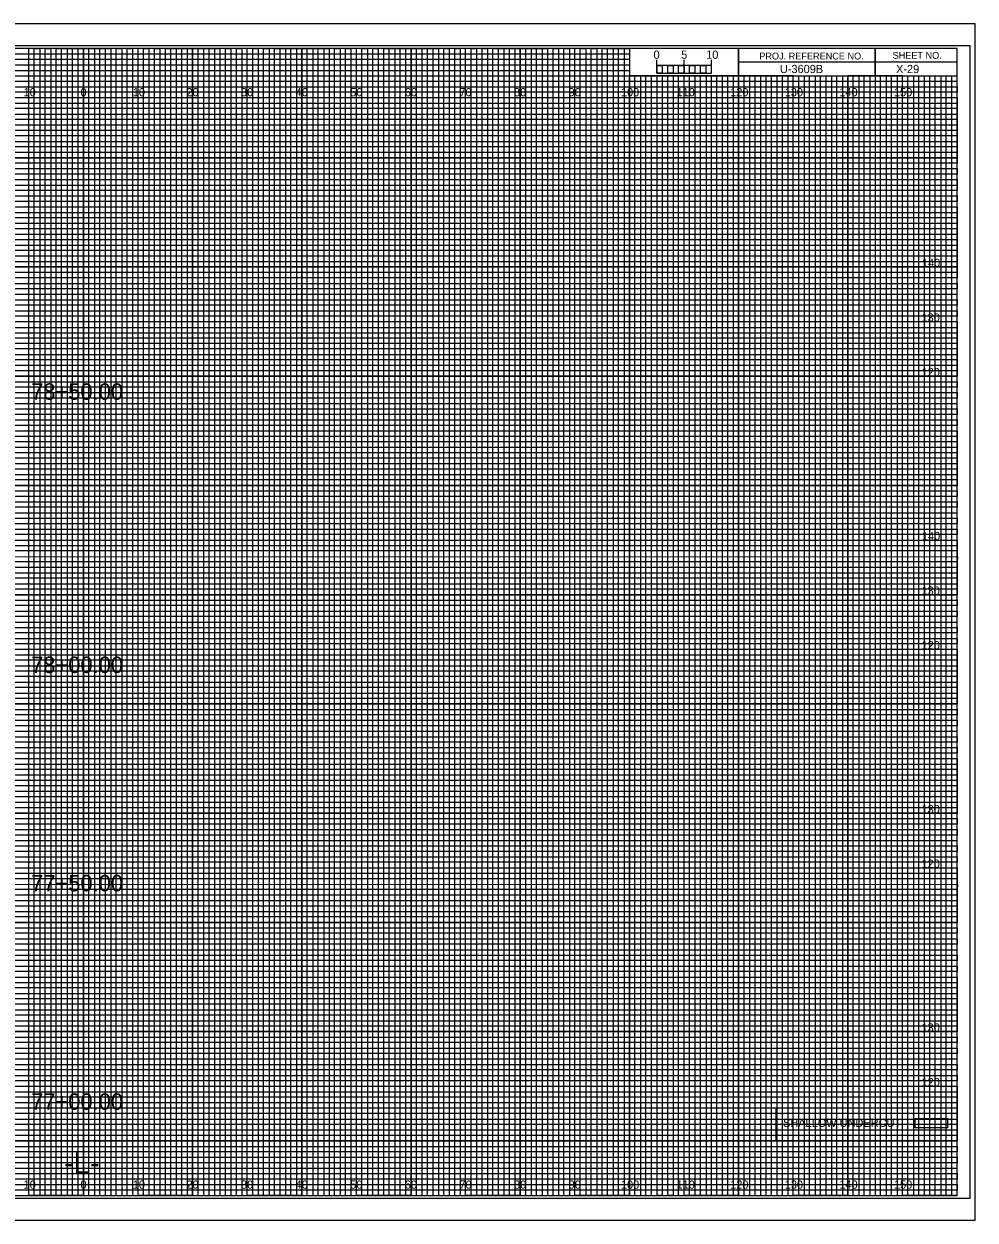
# Model space of a CAD drawing. Extents: x -13 to 329, y -17 to 10994.
# Drawn here: x 149.1 to 323.3, y 5935.5 to 6154.5 of the extents above; entities that cross this region are included whole.
import ezdxf

# ---------------------------------------------------------------- set-up
doc = ezdxf.new("R2010")
doc.units = 0
for name, color, linetype in [('Prop DSN Text', 7, 'Continuous'), ('Prop Grid Mask', 7, 'Continuous'), ('Prop Road Plan_ Recs - UC Shallow (pattern)', 7, 'Continuous'), ('Prop XS Alignment Label', 7, 'Continuous'), ('Prop XS Bar Scale Labels', 7, 'Continuous'), ('Prop XS Elevation Labels', 7, 'Continuous'), ('Prop XS Offset Labels', 7, 'Continuous'), ('Prop XS Project Number', 7, 'Continuous'), ('Prop XS Sheet Number', 7, 'Continuous'), ('Prop XS Station Labels', 7, 'Continuous'), ('Sheet Cross Section CELL', 7, 'Continuous'), ('Sheet Cross Section Grid Major CELL', 7, 'Continuous'), ('Sheet Cross Section Grid Middle CELL', 7, 'Continuous'), ('Sheet Cross Section Grid Minor 1 CELL', 7, 'Continuous'), ('Sheet Cross Section Grid Minor 2 CELL', 7, 'Continuous'), ('Sheet Cross Section Scale CELL', 7, 'Continuous'), ('Sheet Cutting Line CELL', 7, 'Continuous'), ('Sheet DOT Grid CELL', 7, 'Continuous'), ('Sheet Plot Border Inside CELL', 7, 'Continuous'), ('Sheet Plot Border Outside CELL', 7, 'Continuous')]:
    doc.layers.add(name, color=color, linetype=linetype)

msp = doc.modelspace()

# ---------------------------------------------------------------- linework, layer by layer
at = {"layer": 'Prop Grid Mask'}
msp.add_lwpolyline([(286.89, 5956.03), (320, 5956.03), (320, 5950), (286.89, 5950)], close=True, dxfattribs=at)
at = {"layer": 'Prop Road Plan_ Recs - UC Shallow (pattern)'}
msp.add_lwpolyline([(312.34, 5954.08), (318.23, 5954.08), (318.23, 5952.36), (312.34, 5952.36)], close=True, dxfattribs=at)
at = {"layer": 'Sheet Cross Section CELL'}
for p, q in [((305, 6150), (305, 6145)), ((305, 6145), (305, 6150)), ((280, 6147.5), (280, 6145)), ((320, 6147.49), (280, 6147.49)), ((280, 6145), (320, 6145))]:
    msp.add_line(p, q, dxfattribs=at)
for points in [[(320, 6150), (0, 6150), (0, 5940), (320, 5940)], [(280, 6150), (260, 6150), (260, 6145.03), (280, 6145.03)], [(320, 6150), (280, 6150), (280, 6145), (320, 6145)]]:
    msp.add_lwpolyline(points, close=True, dxfattribs=at)
at = {"layer": 'Sheet Cross Section Grid Major CELL'}
for p, q in [((150, 6150), (140, 6150)), ((150, 5940), (150, 6150)), ((170, 6150), (160, 6150)), ((160, 6150), (160, 5940)), ((170, 5940), (170, 6150)), ((190, 6150), (180, 6150)), ((180, 6150), (180, 5940)), ((190, 5940), (190, 6150)), ((210, 6150), (200, 6150)), ((200, 6150), (200, 5940)), ((210, 5940), (210, 6150)), ((230, 6150), (220, 6150)), ((220, 6150), (220, 5940)), ((230, 5940), (230, 6150)), ((250, 6150), (240, 6150)), ((240, 6150), (240, 5940)), ((250, 5940), (250, 6150)), ((260, 6150), (260, 5940)), ((270, 5940), (270, 6145)), ((290, 6145), (280, 6145)), ((280, 6145), (280, 5940)), ((290, 5940), (290, 6145)), ((310, 6145), (300, 6145)), ((300, 6145), (300, 5940)), ((310, 5940), (310, 6145)), ((160, 5940), (150, 5940)), ((180, 5940), (170, 5940)), ((200, 5940), (190, 5940)), ((220, 5940), (210, 5940)), ((240, 5940), (230, 5940)), ((260, 5940), (250, 5940)), ((280, 5940), (270, 5940)), ((300, 5940), (290, 5940)), ((320, 5940), (310, 5940)), ((320, 5940), (320, 5940))]:
    msp.add_line(p, q, dxfattribs=at)
for points in [[(0, 6140), (320, 6140), (320, 6130), (0, 6130)], [(0, 6120), (320, 6120), (320, 6110), (0, 6110)], [(0, 6100), (320, 6100), (320, 6090), (0, 6090)], [(0, 6080), (320, 6080), (320, 6070), (0, 6070)], [(0, 6060), (320, 6060), (320, 6050), (0, 6050)], [(0, 6040), (320, 6040), (320, 6030), (0, 6030)], [(0, 6020), (320, 6020), (320, 6010), (0, 6010)], [(0, 6000), (320, 6000), (320, 5990), (0, 5990)], [(0, 5980), (320, 5980), (320, 5970), (0, 5970)], [(0, 5960), (320, 5960), (320, 5950), (0, 5950)]]:
    msp.add_lwpolyline(points, dxfattribs=at)
at = {"layer": 'Sheet Cross Section Grid Middle CELL'}
for points in [[(145, 5940), (155, 5940), (155, 6150), (165, 6150), (165, 5940), (175, 5940), (175, 6150), (185, 6150), (185, 5940), (195, 5940), (195, 6150), (205, 6150), (205, 5940), (215, 5940), (215, 6150), (225, 6150), (225, 5940), (235, 5940), (235, 6150), (245, 6150), (245, 5940), (255, 5940), (255, 6150), (259.93, 6150), (260, 6150), (260, 6145), (264.99, 6145), (264.99, 5940), (275, 5940), (275, 6145), (285, 6145), (285, 5940), (295, 5940), (295, 6145), (305, 6145), (305, 5940), (315, 5940), (315, 6145)], [(0, 6145), (275, 6145)], [(0, 6125), (320, 6125), (320, 6135), (0, 6135)], [(0, 6105), (320, 6105), (320, 6115), (0, 6115)], [(0, 6085), (320, 6085), (320, 6095), (0, 6095)], [(0, 6065), (320, 6065), (320, 6075), (0, 6075)], [(0, 6045), (320, 6045), (320, 6055), (0, 6055)], [(0, 6025), (320, 6025), (320, 6035), (0, 6035)], [(0, 6005), (320, 6005), (320, 6015), (0, 6015)], [(0, 5985), (320, 5985), (320, 5995), (0, 5995)], [(0, 5965), (320, 5965), (320, 5975), (0, 5975)], [(0, 5945), (320, 5945), (320, 5955), (0, 5955)]]:
    msp.add_lwpolyline(points, dxfattribs=at)
at = {"layer": 'Sheet Cross Section Grid Minor 1 CELL'}
for p, q in [((0, 6149), (260, 6149)), ((260, 6147.98), (0, 6147.98)), ((260, 6149), (260, 6147.98)), ((0, 6147), (260, 6147)), ((260, 6145.89), (0, 6145.89)), ((260, 6147), (260, 6145.89)), ((0, 6144), (320, 6144))]:
    msp.add_line(p, q, dxfattribs=at)
for points in [[(0, 6143), (270, 6143), (320, 6143), (320, 6142), (0, 6142)], [(0, 6141), (320, 6141), (320, 6139), (0, 6139)], [(0, 6138), (320, 6138), (320, 6137), (0, 6136.98)], [(0, 6136), (320, 6136), (320, 6134), (0, 6134)], [(0, 6133), (320, 6133), (320, 6132), (0, 6132)], [(0, 6131), (320, 6131), (320, 6129), (0, 6129)], [(0, 6128), (320, 6128), (320, 6127), (0, 6127)], [(0, 6126), (320, 6126), (320, 6124), (0, 6124)], [(0, 6123), (320, 6123), (320, 6122), (0, 6122)], [(0, 6121), (320, 6121), (320, 6119), (0, 6119)], [(0, 6118), (320, 6118), (320, 6117), (0, 6117)], [(0, 6116), (320, 6116), (320, 6113.95), (320, 6113), (320, 6112), (0, 6112)], [(0, 6114), (320, 6114), (320, 6113), (0, 6113)], [(0, 6111), (320, 6111), (320, 6109), (0, 6109.03)], [(0, 6109.03), (320, 6109), (320, 6108), (0, 6108)], [(0, 6107), (320, 6107), (320, 6106), (0, 6106)], [(0, 6104), (320, 6104), (320, 6103), (0, 6103)], [(0, 6102), (320, 6102), (320, 6101), (0, 6101)], [(-0.07, 6098.89), (320, 6098.89), (320, 6097.88), (-0.07, 6097.88)], [(0, 6097), (320, 6097), (320, 6096), (0, 6096)], [(0, 6094), (320, 6094), (320, 6093), (0, 6093)], [(0, 6092), (320, 6092), (320, 6091), (0, 6091)], [(0, 6089), (320, 6089), (320, 6088), (0, 6088)], [(0, 6087), (320, 6087), (320, 6086), (0, 6086)], [(0, 6084), (320, 6084), (320, 6083), (0, 6083)], [(0, 6082), (320, 6082), (320, 6081), (0, 6081)], [(0, 6079), (320, 6079), (319.99, 6077.98), (0, 6078)], [(0, 6077), (320, 6077), (320, 6076), (0, 6076)], [(0, 6074), (320, 6074), (320, 6073), (0, 6073)], [(0, 6072), (320, 6072), (320, 6071), (0, 6071)], [(0, 6069), (320, 6069), (320, 6068), (0, 6068)], [(0, 6067), (320, 6067), (320, 6066), (0, 6066)], [(0, 6064), (320, 6064), (320, 6063), (0, 6063)], [(0, 6062), (320, 6062), (320, 6061), (0, 6061)], [(0, 6059), (320, 6059), (320, 6058), (0, 6058)], [(0, 6056.99), (320.07, 6056.91), (320, 6056), (0, 6056)], [(0, 6054), (320, 6054), (320, 6053), (0, 6053)], [(0, 6052), (320, 6052), (320, 6051), (0, 6051)], [(0, 6049), (320, 6049), (320, 6048), (0, 6048)], [(0, 6047), (320, 6047), (320, 6046), (0, 6046)], [(0, 6044), (320, 6044), (320, 6043), (0, 6043)], [(0, 6042), (320, 6042), (320, 6041), (0, 6041)], [(0, 6039), (320, 6039), (320, 6038), (0, 6038)], [(0, 6037), (320, 6037), (320, 6036), (0, 6036)], [(0, 6034), (320, 6034), (320, 6033), (0, 6033)], [(0, 6032), (320, 6032), (320, 6031), (0, 6031)], [(0, 6029), (320, 6029), (320, 6028), (0, 6028)], [(0, 6027), (320, 6027), (320, 6026), (0, 6026)], [(0, 6024), (320, 6024), (320, 6023), (0, 6023)], [(0, 6022), (320, 6022), (320, 6021), (0, 6021)], [(0, 6019), (320, 6019), (319.99, 6017.98), (0, 6018)], [(0, 6017), (320, 6017), (320, 6016), (0, 6016)], [(0, 6014), (320, 6014), (320, 6013), (0, 6013)], [(0, 6012), (320, 6012), (320, 6011), (0, 6011)], [(0, 6009), (320, 6009), (320, 6008), (0, 6008)], [(0, 6007), (320, 6007), (320, 6006), (0, 6006)], [(0, 6004), (320, 6004), (320, 6003), (0, 6003)], [(0, 6002), (320, 6002), (320, 6001), (0, 6001)], [(0, 5999), (320, 5999), (320, 5998), (0, 5998)], [(0, 5996.99), (320.07, 5996.91), (320, 5996), (0, 5996)], [(0, 5994), (320, 5994), (320, 5993), (0, 5993)], [(0, 5992), (320, 5992), (320, 5991), (0, 5991)], [(0, 5989), (320, 5989), (320, 5988), (0, 5988)], [(0, 5987), (320, 5987), (320, 5986), (0, 5986)], [(0, 5984), (320, 5984), (320, 5983), (0, 5983)], [(0, 5982), (320, 5982), (320, 5981), (0, 5981)], [(0, 5979), (320, 5979), (320, 5978), (0, 5978)], [(0, 5977), (320, 5977), (320, 5976), (0, 5976)], [(0, 5974), (320, 5974), (320, 5973), (0, 5973)], [(0, 5972), (320, 5972), (320, 5971), (0, 5971)], [(0, 5969), (320, 5969), (320, 5968), (0, 5968)], [(0, 5967), (320, 5967), (320, 5966), (0, 5966)], [(0, 5964), (320, 5964), (320, 5963), (0, 5963)], [(0, 5962), (320, 5962), (320, 5961), (0, 5961)], [(0, 5959), (320, 5959), (320, 5958), (0, 5958)], [(0, 5957), (320, 5957), (320, 5956), (0, 5956)], [(0, 5954), (320, 5954), (320, 5953), (0, 5953)], [(0, 5952), (320, 5952), (320, 5951), (0, 5951)], [(0, 5949), (320, 5949), (320, 5948), (0, 5948)], [(0, 5947), (320, 5947), (320, 5946), (0, 5946)], [(0, 5944), (320, 5944), (320, 5943), (0, 5943)], [(0, 5942), (320, 5942), (320, 5941), (0, 5941)]]:
    msp.add_lwpolyline(points, dxfattribs=at)
at = {"layer": 'Sheet Cross Section Grid Minor 2 CELL'}
for p, q in [((267, 6145), (266.01, 6145)), ((266.01, 6145), (266.01, 5940)), ((267, 5940), (267, 6145)), ((269, 6145), (268, 6145)), ((268, 6145), (268, 5940)), ((269, 5940), (269, 6145)), ((266.01, 5940), (265, 5940)), ((268, 5940), (267, 5940))]:
    msp.add_line(p, q, dxfattribs=at)
for points in [[(150, 5940), (151, 5940), (151, 6150), (152, 6150), (152, 5940)], [(152, 5940), (153, 5940), (153, 6150), (154, 6150), (154, 5940)], [(155, 5940), (156, 5940), (156, 6150), (157, 6150), (157, 5940)], [(157, 5940), (158, 5940), (158, 6150), (159, 6150), (159, 5940)], [(160, 5940), (161, 5940), (161, 6150), (162, 6150), (162, 5940)], [(162, 5940), (163, 5940), (163, 6150), (164, 6150), (164, 5940)], [(165, 5940), (166, 5940), (166, 6150), (167, 6150), (167, 5940)], [(167, 5940), (168, 5940), (168, 6150), (169, 6150), (169, 5940)], [(170, 5940), (171, 5940), (171, 6150), (172, 6150), (172, 5940)], [(172, 5940), (173, 5940), (173, 6150), (174, 6150), (174, 5940)], [(175, 5940), (176, 5940), (176, 6150), (177, 6150), (177, 5940)], [(177, 5940), (178, 5940), (178, 6150), (179, 6150), (179, 5940)], [(180, 5940), (181, 5940), (181, 6150), (182, 6150), (182, 5940)], [(182, 5940), (183, 5940), (183, 6150), (184, 6150), (184, 5940)], [(185, 5940), (186, 5940), (186, 6150), (187, 6150), (187, 5940)], [(187, 5940), (188, 5940), (188, 6150), (189, 6150), (189, 5940)], [(190, 5940), (191, 5940), (191, 6150), (192, 6150), (192, 5940)], [(192, 5940), (193, 5940), (193, 6150), (194, 6150), (194, 5940)], [(195, 5940), (196, 5940), (196, 6150), (197, 6150), (197, 5940)], [(197, 5940), (198, 5940), (198, 6150), (199, 6150), (199, 5940)], [(200, 5940), (201, 5940), (201, 6150), (202, 6150), (202, 5940)], [(202, 5940), (203, 5940), (203, 6150), (204, 6150), (204, 5940)], [(205, 5940), (206, 5940), (206, 6150), (207, 6150), (207, 5940)], [(207, 5940), (208, 5940), (208, 6150), (209, 6150), (209, 5940)], [(210, 5940), (211, 5940), (211, 6150), (212, 6150), (212, 5940)], [(212, 5940), (213, 5940), (213, 6150), (214, 6150), (214, 5940)], [(215, 5940), (216, 5940), (216, 6150), (217, 6150), (217, 5940)], [(217, 5940), (218, 5940), (218, 6150), (219, 6150), (219, 5940)], [(220, 5940), (221, 5940), (221, 6150), (222, 6150), (222, 5940)], [(222, 5940), (223, 5940), (223, 6150), (224, 6150), (224, 5940)], [(225, 5940), (226, 5940), (226, 6150), (227, 6150), (227, 5940)], [(227, 5940), (228, 5940), (228, 6150), (229, 6150), (229, 5940)], [(230, 5940), (231, 5940), (231, 6150), (232, 6150), (232, 5940)], [(232, 5940), (233, 5940), (233, 6150), (234, 6150), (234, 5940)], [(235, 5940), (236, 5940), (236, 6150), (237, 6150), (237, 5940)], [(237, 5940), (238, 5940), (238, 6150), (239, 6150), (239, 5940)], [(240, 5940), (241, 5940), (241, 6150), (242, 6150), (242, 5940)], [(242, 5940), (243, 5940), (243, 6150), (244, 6150), (244, 5940)], [(245, 5940), (246, 5940), (246, 6150), (247, 6150), (247, 5940)], [(247, 5940), (248, 5940), (248, 6150), (249, 6150), (249, 5940)], [(250, 5940), (251, 5940), (251, 6150), (252, 6150), (252, 5940)], [(252, 5940), (253, 5940), (253, 6150), (254, 6150), (254, 5940)], [(255, 5940), (256, 5940), (256, 6150), (257, 6150), (257, 5940)], [(257, 5940), (258, 5940), (258, 6150), (259, 6150), (259, 5940)], [(260, 5940), (261, 5940), (261, 6145), (262.02, 6145), (262.02, 5940)], [(262, 5940), (263, 5940), (263, 6145), (263.99, 6145), (263.99, 5940)], [(270, 5940), (270.98, 5940), (270.98, 6145), (272, 6145), (272, 5940)], [(272, 5940), (273, 5940), (273, 6145), (274.05, 6145), (274.05, 5940)], [(275, 5940), (276, 5940), (276, 6145), (277, 6145), (277, 5940)], [(277, 5940), (278, 5940), (278, 6145), (279, 6145), (279, 5940)], [(280, 5940), (281, 5940), (281, 6145), (282, 6145), (282, 5940)], [(282, 5940), (283, 5940), (283, 6145), (284, 6145), (284, 5940)], [(285, 5940), (286, 5940), (286, 6145), (287, 6145), (287, 5940)], [(287, 5940), (288, 5940), (288, 6145), (289, 6145), (289, 5940)], [(290, 5940), (291, 5940), (291, 6145), (292, 6145), (292, 5940)], [(292, 5940), (293, 5940), (293, 6145), (294, 6145), (294, 5940)], [(295, 5940), (296, 5940), (296, 6145), (297, 6145), (297, 5940)], [(297, 5940), (298, 5940), (298, 6145), (299, 6145), (299, 5940)], [(300, 5940), (301, 5940), (301, 6145), (302, 6145), (302, 5940)], [(302, 5940), (303, 5940), (303, 6145), (304, 6145), (304, 5940)], [(305, 5940), (306, 5940), (306, 6145), (307, 6145), (307, 5940)], [(307, 5940), (308, 5940), (308, 6145), (309, 6145), (309, 5940)], [(310, 5940), (311, 5940), (311, 6145), (312, 6145), (312, 5940)], [(312, 5940), (313, 5940), (313, 6145), (314, 6145), (314, 5940)], [(315, 5940), (316, 5940), (316, 6145), (317, 6145), (317, 5940)], [(317, 5940), (318, 5940), (318, 6145), (319, 6145), (319, 5940)]]:
    msp.add_lwpolyline(points, dxfattribs=at)
at = {"layer": 'Sheet Cross Section Scale CELL'}
for p, q in [((265, 6145.49), (265, 6147.9)), ((265, 6146.9), (265, 6147.9)), ((270, 6145.49), (270, 6147.9)), ((275, 6145.49), (275, 6147.9)), ((275, 6146.9), (275, 6147.9))]:
    msp.add_line(p, q, dxfattribs=at)
for points in [[(275, 6146.9), (265, 6146.9), (265, 6145.49), (275, 6145.49)], [(265, 6146.9), (266, 6146.9), (266, 6145.49), (265, 6145.49)], [(267, 6146.9), (268, 6146.9), (268, 6145.49), (267, 6145.49)], [(269, 6146.9), (270, 6146.9), (270, 6145.49), (269, 6145.49)], [(271, 6146.9), (272, 6146.9), (272, 6145.49), (271, 6145.49)], [(273, 6146.9), (274, 6146.9), (274, 6145.49), (273, 6145.49)]]:
    msp.add_lwpolyline(points, close=True, dxfattribs=at)
at = {"layer": 'Sheet Cutting Line CELL'}
for p, q in [((323.3, 6154.5), (-13.4, 6154.5)), ((-13.4, 5935.5), (323.3, 5935.5))]:
    msp.add_line(p, q, dxfattribs=at)
at = {"layer": 'Sheet DOT Grid CELL'}
for p, q in [((150, 5940), (150, 6150)), ((160, 5940), (160, 6150)), ((170, 5940), (170, 6150)), ((180, 5940), (180, 6150)), ((190, 5940), (190, 6150)), ((200, 5940), (200, 6150)), ((210, 5940), (210, 6150)), ((220, 5940), (220, 6150)), ((230, 5940), (230, 6150)), ((240, 5940), (240, 6150)), ((250, 5940), (250, 6150)), ((260, 5940), (260, 6144.69)), ((270, 5940), (270, 6144.69)), ((280, 5940), (280, 6144.69)), ((290, 5940), (290, 6144.69)), ((300, 5940), (300, 6144.69)), ((310, 5940), (310, 6144.69)), ((0, 6140), (320, 6140)), ((0, 6130), (320, 6130)), ((0, 6120), (320, 6120)), ((0, 6110), (320, 6110)), ((0, 6100), (320, 6100)), ((0, 6090), (320, 6090)), ((0, 6080), (320, 6080)), ((0, 6070), (320, 6070)), ((0, 6060), (320, 6060)), ((0, 6050), (320, 6050)), ((0, 6040), (320, 6040)), ((0, 6030), (320, 6030)), ((0, 6020), (320, 6020)), ((0, 6010), (320, 6010)), ((0, 6000), (320, 6000)), ((0, 5990), (320, 5990)), ((0, 5980), (320, 5980)), ((0, 5970), (320, 5970)), ((0, 5960), (320, 5960)), ((0, 5950), (320, 5950))]:
    msp.add_line(p, q, dxfattribs=at)
at = {"layer": 'Sheet Plot Border Inside CELL'}
msp.add_lwpolyline([(-10.8, 5939.5), (322.4, 5939.5), (322.4, 6150.5), (-10.8, 6150.5)], close=True, dxfattribs=at)
at = {"layer": 'Sheet Plot Border Outside CELL'}
msp.add_lwpolyline([(-13.4, 5935.5), (323.3, 5935.5), (323.3, 6154.5), (-13.4, 6154.5)], close=True, dxfattribs=at)

# ---------------------------------------------------------------- texts
at = {"layer": 'Prop DSN Text'}
msp.add_text('SHALLOW UNDERCUT', height=1.5, dxfattribs=at).set_placement((288.13, 5952.55))
at = {"layer": 'Prop XS Alignment Label'}
msp.add_text('-L-', height=4, dxfattribs=at).set_placement((156.42, 5944))
at = {"layer": 'Prop XS Bar Scale Labels'}
for s, p in [('5', (269.47, 6148.12)), ('10', (274.04, 6148.12))]:
    msp.add_text(s, height=1.5, dxfattribs=at).set_placement(p)
at = {"layer": 'Prop XS Elevation Labels'}
for s, p in [('140', (313.57, 6110)), ('130', (313.49, 6100)), ('120', (313.5, 6090)), ('140', (313.57, 6060)), ('130', (313.49, 6050)), ('120', (313.5, 6040)), ('130', (313.49, 6010)), ('120', (313.5, 6000)), ('130', (313.49, 5970)), ('120', (313.5, 5960))]:
    msp.add_text(s, height=1.5, dxfattribs=at).set_placement(p)
at = {"layer": 'Prop XS Offset Labels'}
for s, p in [('10', (149.04, 6141.25)), ('0', (159.45, 6141.25)), ('0', (159.45, 6141.25)), ('10', (169.04, 6141.25)), ('20', (178.86, 6141.25)), ('30', (188.86, 6141.25)), ('40', (198.86, 6141.25)), ('50', (208.86, 6141.25)), ('60', (218.86, 6141.25)), ('70', (228.86, 6141.25)), ('80', (238.86, 6141.25)), ('90', (248.86, 6141.25)), ('100', (258.44, 6141.25)), ('110', (268.62, 6141.25)), ('120', (278.44, 6141.25)), ('130', (288.44, 6141.25)), ('140', (298.44, 6141.25)), ('150', (308.44, 6141.25)), ('10', (149.04, 5941.25)), ('0', (159.45, 5941.25)), ('0', (159.45, 5941.25)), ('10', (169.04, 5941.25)), ('20', (178.86, 5941.25)), ('30', (188.86, 5941.25)), ('40', (198.86, 5941.25)), ('50', (208.86, 5941.25)), ('60', (218.86, 5941.25)), ('70', (228.86, 5941.25)), ('80', (238.86, 5941.25)), ('90', (248.86, 5941.25)), ('100', (258.44, 5941.25)), ('110', (268.62, 5941.25)), ('120', (278.44, 5941.25)), ('130', (288.44, 5941.25)), ('140', (298.44, 5941.25)), ('150', (308.44, 5941.25))]:
    msp.add_text(s, height=1.5, dxfattribs=at).set_placement(p)
at = {"layer": 'Prop XS Project Number'}
msp.add_text('U-3609B', height=1.5, dxfattribs=at).set_placement((287.56, 6145.5))
at = {"layer": 'Prop XS Sheet Number'}
msp.add_text('X-29', height=1.5, dxfattribs=at).set_placement((308.83, 6145.5))
at = {"layer": 'Prop XS Station Labels'}
for s, p in [('78+50.00', (150.41, 6085.69)), ('78+00.00', (150.41, 6035.66)), ('77+50.00', (150.41, 5995.69)), ('77+00.00', (150.41, 5955.7))]:
    msp.add_text(s, height=3, dxfattribs=at).set_placement(p)
at = {"layer": 'Sheet Cross Section CELL'}
for s, p in [('PROJ. REFERENCE NO.', (283.77, 6147.99)), ('SHEET NO.', (308.19, 6148.12))]:
    msp.add_text(s, height=1.25, dxfattribs=at).set_placement(p)
at = {"layer": 'Sheet Cross Section Scale CELL'}
msp.add_text('0', height=1.5, dxfattribs=at).set_placement((264.41, 6148.12))

doc.saveas('drawing.dxf')
